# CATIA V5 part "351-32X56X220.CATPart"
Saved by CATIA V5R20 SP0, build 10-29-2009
Part number: 351-32X56X220
Definition: NONE
Nomenclature: 351-32X56X220
Source: Unknown
Description: 351-32X56X220
Bounding box of the stored display mesh (mm): x -7 to 213, y -22.5 to 22.5, z -22.5 to 22.5
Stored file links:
  C:\Users\Utente\Desktop\IO LAVORO\3D X SITO CF\X SITO\PLASTICA\351\351-32X56X220.CATPart
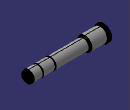
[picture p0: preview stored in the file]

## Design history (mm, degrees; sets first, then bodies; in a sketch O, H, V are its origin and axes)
Body1 "351-32X56X220" (main body)
  Solid1: solid without history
